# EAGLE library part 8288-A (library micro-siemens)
MICROPROCESSOR/PERIPHERAL DEVICE
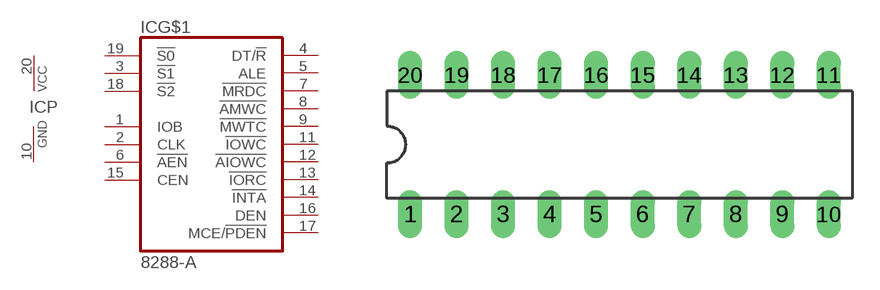
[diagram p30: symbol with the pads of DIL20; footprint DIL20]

Designator prefix IC; gates G$1=8288-A P=VCCGND

## 8288-A (OC_FARNELL: unknown; OC_NEWARK: unknown)  [DIL20]
1  G$1:IOB  in
2  G$1:CLK  in
3  G$1:!S1  in
4  G$1:DT/!R  out
5  G$1:ALE  out
6  G$1:!AEN  in
7  G$1:!MRDC  out
8  G$1:!AMWC  out
9  G$1:!MWTC  out
10  P:GND  pwr
11  G$1:!IOWC  out
12  G$1:!AIOWC  out
13  G$1:!IORC  out
14  G$1:!INTA  out
15  G$1:CEN  in
16  G$1:DEN  out
17  G$1:MCE/!PDEN  out
18  G$1:!S2  in
19  G$1:!S0  in
20  P:VCC  pwr

## Footprint DIL20 (pad centres in mm)
Dual In Line Package
drill 0.813 long: 1 -11.43,-3.81; 2 -8.89,-3.81; 3 -6.35,-3.81; 4 -3.81,-3.81; 5 -1.27,-3.81; 6 1.27,-3.81; 7 3.81,-3.81; 8 6.35,-3.81; 9 8.89,-3.81; 10 11.43,-3.81; 11 11.43,3.81; 12 8.89,3.81; 13 6.35,3.81; 14 3.81,3.81; 15 1.27,3.81; 16 -1.27,3.81; 17 -3.81,3.81; 18 -6.35,3.81; 19 -8.89,3.81; 20 -11.43,3.81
